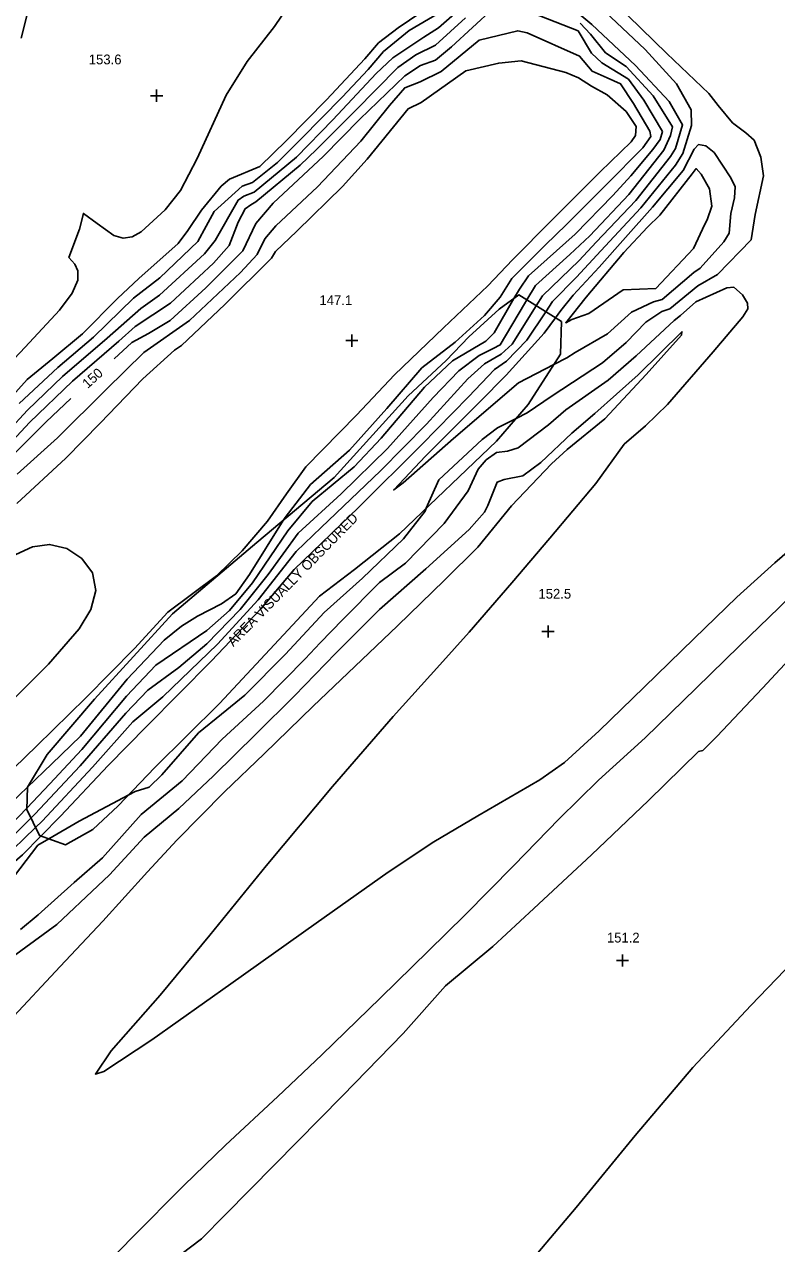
# Model space of a CAD drawing. Extents: x 1475150 to 2003689, y 770235 to 1112803.
# Drawn here: x 2002077.7 to 2002231.5, y 772192.1 to 772441.5 of the extents above; entities that cross this region are included whole.
import ezdxf

# ---------------------------------------------------------------- set-up
doc = ezdxf.new("R2010")
doc.units = 0
for name, color, linetype in [('RD_DTM_Major1', 7, 'Continuous'), ('RD_DTM_Major1_Lbl', 7, 'Continuous'), ('RD_DTM_Major2', 7, 'Continuous'), ('RD_DTM_Minor1', 7, 'Continuous'), ('RD_DTM_Minor2', 7, 'Continuous'), ('RD_DTM_Obscure', 7, 'Continuous'), ('RD_DTM_Spot_Elev', 7, 'Continuous'), ('RD_TX_Misc1', 7, 'Continuous')]:
    doc.layers.add(name, color=color, linetype=linetype)

msp = doc.modelspace()

# ---------------------------------------------------------------- linework, layer by layer
at = {"layer": 'RD_DTM_Major1'}
for points in [[(2002096.04, 772373.12), (2002099.71, 772376.42), (2002103.12, 772378.27), (2002107.53, 772380.93), (2002114.78, 772387.62), (2002122.38, 772395.21), (2002125.05, 772400.79), (2002128.57, 772404.93), (2002138.89, 772414.53), (2002146.31, 772422.13), (2002155.47, 772431), (2002158.68, 772433.07), (2002161.76, 772434.21), (2002165.01, 772436.89), (2002173.6, 772444.79)], [(2002179.95, 772444.48), (2002190.92, 772440.2), (2002193.69, 772435.61), (2002195.75, 772433.64), (2002201.26, 772430.28), (2002204.37, 772426.01), (2002208.16, 772419.59), (2002207.7, 772417.93), (2002206.18, 772415.89), (2002201.68, 772410.53), (2002198.01, 772406.51), (2002190.33, 772398.57), (2002180.81, 772390.09), (2002178.92, 772387.35), (2002177.81, 772385.43)], [(2002217.31, 772401.51), (2002218.28, 772404.32), (2002217.81, 772407.84), (2002216.1, 772410.85), (2002215.09, 772411.99), (2002214.27, 772410.95), (2002207.62, 772402.48), (2002205.14, 772400.05), (2002200.29, 772394.87), (2002192.57, 772385.71), (2002188.41, 772380.47), (2002189.65, 772381.12), (2002193.13, 772382.33), (2002200.14, 772387.17), (2002206.84, 772387.49), (2002214.51, 772395.67), (2002216.84, 772400.64), (2002217.31, 772401.51)], [(2002074.09, 772352.16), (2002082.18, 772360.19), (2002087.21, 772364.99)], [(2002078.21, 772281.19), (2002073.27, 772275.97)]]:
    msp.add_lwpolyline(points, dxfattribs=at)
at = {"layer": 'RD_DTM_Major2'}
msp.add_lwpolyline([(2002177.81, 772385.43), (2002173.77, 772378.43), (2002172.03, 772376.73), (2002165.24, 772372.7), (2002159.55, 772367.31), (2002150.66, 772356.85), (2002145.16, 772350.99), (2002136.57, 772343.89), (2002131.55, 772337.92), (2002124.34, 772327.25), (2002119.68, 772321.58), (2002114.99, 772317.49), (2002104.6, 772310.41), (2002098.59, 772304.06), (2002089.45, 772293.19), (2002082.92, 772286.17), (2002078.21, 772281.19)], dxfattribs=at)
at = {"layer": 'RD_DTM_Minor1'}
for points in [[(2002131.59, 772445.11), (2002128.82, 772441.07), (2002123.24, 772433.92), (2002118.98, 772427), (2002113.04, 772414.08), (2002109.63, 772407.52), (2002106.51, 772403.59), (2002101.57, 772399.04), (2002099.77, 772398.07), (2002097.91, 772397.78), (2002096.02, 772398.33), (2002092.6, 772400.79), (2002089.79, 772402.84), (2002088.99, 772399.64), (2002086.83, 772393.81), (2002088.06, 772392.44), (2002088.65, 772391.12), (2002088.61, 772389.2), (2002087.46, 772386.52), (2002084.9, 772383.04), (2002077.87, 772375.5), (2002071.07, 772368.29), (2002063.39, 772359.35)], [(2002071.11, 772360.96), (2002078.3, 772368.83), (2002083.55, 772373.16), (2002089.61, 772378.22), (2002096.76, 772385.42), (2002101.13, 772389.51), (2002109.13, 772396.69), (2002111.13, 772399.33), (2002113.95, 772403.51), (2002117.98, 772408.38), (2002119.66, 772409.86), (2002125.85, 772412.44), (2002131.34, 772417.74), (2002139.46, 772426.08), (2002147.34, 772434.43), (2002150.13, 772437.76), (2002154.11, 772440.78), (2002163.58, 772447.26)], [(2002078.7, 772445.16), (2002077.07, 772438.66)], [(2002189.74, 772444.85), (2002193.77, 772441.47), (2002202.64, 772433.09), (2002209.55, 772425.74), (2002212.28, 772420.92), (2002210.82, 772416.09), (2002209.84, 772414.47), (2002202.73, 772405.48), (2002194.62, 772396.92), (2002191.18, 772393.22), (2002183.65, 772386), (2002182.36, 772383.94)], [(2002070.24, 772353.89), (2002078.33, 772362.6), (2002085.51, 772369.5), (2002094.66, 772377.31), (2002101.52, 772383.41), (2002105.35, 772386.08), (2002114.53, 772394.57), (2002116.75, 772397.28), (2002121.43, 772405.55), (2002122.61, 772406.36), (2002124.69, 772407.19), (2002133.34, 772414.37), (2002140.79, 772422), (2002149.66, 772431.44), (2002153.02, 772434.67), (2002159.41, 772438.86), (2002162.38, 772440.8), (2002166.23, 772444.11)], [(2002071.72, 772352.54), (2002078.79, 772360.03), (2002087.55, 772368.55), (2002097.04, 772376.73), (2002100.34, 772379.71), (2002107.59, 772384.5), (2002116.35, 772392.69), (2002119.57, 772396.26), (2002121.44, 772401.04), (2002122.88, 772403.8), (2002124.04, 772404.56), (2002125.01, 772405.23), (2002134.13, 772412.67), (2002137.47, 772415.91), (2002145.32, 772423.85), (2002154.08, 772432.7), (2002157.78, 772435.3), (2002161.74, 772437.25), (2002167.9, 772442.84)], [(2002076.66, 772363.92), (2002084.53, 772371.33), (2002091.86, 772377.51), (2002100.03, 772385.49), (2002105.41, 772389.65), (2002113.15, 772397.09), (2002114.88, 772400.25), (2002116.55, 772403.2), (2002122.24, 772408.39), (2002124.37, 772409.15), (2002129.48, 772413.28), (2002134.31, 772418.11), (2002142.72, 772426.63), (2002148.01, 772432.3), (2002151.15, 772435.95), (2002156.36, 772440.23), (2002162.35, 772443.76)], [(2002178.25, 772360.88), (2002180.54, 772362.03), (2002185.62, 772365.54), (2002195.92, 772372.24), (2002200.73, 772376.4), (2002204.79, 772380.57), (2002208.08, 772382.75), (2002209.66, 772383.31), (2002215.38, 772388.04), (2002219.45, 772390.32), (2002226.3, 772397.41), (2002227.11, 772402.6), (2002228.85, 772410.53), (2002228.26, 772414.31), (2002226.92, 772417.81), (2002225.23, 772419.29), (2002222.51, 772421.38), (2002219.6, 772424.91), (2002217.66, 772427.33), (2002209.1, 772435.53), (2002201.18, 772443.27)], [(2002196.46, 772444.04), (2002204.64, 772436.37), (2002211.05, 772429.36), (2002214.03, 772424.05), (2002214.12, 772420.83), (2002212.36, 772415.12), (2002210.86, 772412.69), (2002203.76, 772403.97), (2002195.6, 772395.16), (2002190.63, 772389.78), (2002185.71, 772384.8), (2002184.32, 772382.72)], [(2002076.26, 772349.52), (2002084.5, 772356.9), (2002094.41, 772366.82), (2002102.14, 772374.41), (2002111.48, 772380.94), (2002121.91, 772390.77), (2002125.32, 772394.46), (2002126.86, 772397.64), (2002129.1, 772400.27), (2002137.67, 772408.29), (2002146.49, 772417.59), (2002152.34, 772424.9), (2002155.48, 772428.52), (2002158.65, 772429.75), (2002162.91, 772431.86), (2002170.72, 772438.3), (2002178.6, 772440.21), (2002180.5, 772439.79), (2002191.22, 772434.97), (2002193.78, 772431.93), (2002196.88, 772430.55), (2002199.61, 772429.36), (2002202.29, 772425.34), (2002205.62, 772419.68), (2002205.78, 772418.59), (2002204.18, 772416.27), (2002196.71, 772408.74), (2002188.55, 772400.55), (2002184.21, 772396.32), (2002177.4, 772389.54), (2002174.99, 772385.7), (2002171.78, 772381.95), (2002165.77, 772376.49), (2002159.01, 772371.22), (2002151.82, 772362.95), (2002144.17, 772354.4), (2002136.2, 772347.35), (2002131.01, 772340.64), (2002130.62, 772340.02)], [(2002191.35, 772441.74), (2002193.47, 772439.52), (2002196.55, 772435.66), (2002200.75, 772432.87), (2002206.26, 772426.91), (2002210.23, 772420.57), (2002209.84, 772418.8), (2002208.47, 772415.78), (2002201.31, 772406.68), (2002193.3, 772398.24), (2002189.21, 772394.42), (2002182.2, 772388.08), (2002180.45, 772385.13)], [(2002076.18, 772343.51), (2002086.22, 772352.77), (2002093.24, 772359.95), (2002101.96, 772369.01), (2002108.38, 772374.85), (2002109.84, 772375.84), (2002118.72, 772384.18), (2002128.22, 772393.66), (2002129.06, 772395.01), (2002133.39, 772399.19), (2002142.75, 772408.34), (2002147.78, 772413.93), (2002156.15, 772424.23), (2002158.82, 772425.49), (2002167.95, 772432.02), (2002174.72, 772433.57), (2002179.28, 772434.05), (2002188.44, 772431.66), (2002191.04, 772430.57), (2002193.64, 772428.89), (2002196.87, 772427.08), (2002200.75, 772423.69), (2002202.83, 772420.62), (2002202.68, 772418.75), (2002201.77, 772417.45), (2002195.43, 772411.37), (2002185.56, 772401.42), (2002177.5, 772393.35)], [(2002185.96, 772371.92), (2002188.62, 772373.3), (2002190.36, 772374.37), (2002196.91, 772378.19), (2002201.82, 772382.66), (2002206.35, 772384.74), (2002208.1, 772385.25), (2002214.57, 772390.74), (2002215.91, 772391.63), (2002220.73, 772397), (2002221.79, 772398.81), (2002222.17, 772402.85), (2002222.94, 772405.99), (2002223.07, 772408.28), (2002222.15, 772410.12), (2002218.73, 772415.3), (2002217.02, 772416.68), (2002215.56, 772416.91), (2002214.64, 772415.96), (2002212.42, 772411.63), (2002206.12, 772404.1), (2002200.62, 772397.93), (2002195.26, 772391.83), (2002189.91, 772386.1), (2002187.37, 772382.97), (2002186.29, 772381.49)], [(2002177.5, 772393.35), (2002172.48, 772388.05), (2002163.38, 772379.41), (2002153.38, 772369.84), (2002145.64, 772361.53), (2002135.23, 772351.02), (2002131.31, 772345.44), (2002127.39, 772339.88), (2002122.24, 772333.8), (2002116.96, 772328.7), (2002107.03, 772321.27), (2002100.25, 772313.84), (2002090.27, 772303.72), (2002080.25, 772293.93), (2002070.74, 772284.71)], [(2002076.92, 772256.32), (2002080.55, 772259.34), (2002087.89, 772265.99), (2002093.69, 772270.98), (2002101.56, 772279.9), (2002109.98, 772286.79), (2002118.14, 772295.3), (2002126.62, 772303.08), (2002135.13, 772311.7), (2002138.16, 772315.01), (2002142.8, 772319.77), (2002150.35, 772327.3), (2002155.62, 772331.27), (2002163.51, 772339.37), (2002168.48, 772346.09), (2002170.47, 772350.49), (2002172.12, 772352.41), (2002174.23, 772353.91), (2002176.51, 772354.21), (2002178.65, 772354.86), (2002184.91, 772359.58), (2002188.41, 772362.62), (2002197.08, 772368.74), (2002202.77, 772373.71), (2002210.6, 772380.9), (2002211.87, 772381.96), (2002214.99, 772384.72), (2002221.35, 772387.62), (2002222.79, 772387.72), (2002224.51, 772386.19), (2002225.58, 772384.47), (2002225.61, 772383.29), (2002224.59, 772381.66), (2002218.53, 772374.52), (2002209.19, 772363.73), (2002204.69, 772359.36), (2002200.32, 772355.61), (2002194.55, 772347.59), (2002185.12, 772336.39), (2002177.4, 772327.27), (2002168.67, 772317.18), (2002162.64, 772310.49), (2002153.12, 772299.89), (2002140.7, 772285.61), (2002127.14, 772269.36), (2002115.62, 772255.22), (2002105.5, 772242.93), (2002095.45, 772231.51), (2002092.24, 772226.77), (2002093.93, 772227.28), (2002103.79, 772233.79), (2002119.93, 772245.26), (2002137.35, 772257.68), (2002152.06, 772268.07), (2002161.41, 772274.26), (2002170.44, 772279.61), (2002183.09, 772286.99), (2002188.13, 772290.51), (2002195.23, 772296.98), (2002204.43, 772305.9), (2002214.69, 772315.91), (2002223.4, 772324.3), (2002231.13, 772331.38), (2002241.19, 772340.03)], [(2002179.66, 772349.17), (2002183.29, 772351.87), (2002189.64, 772357.85), (2002194.35, 772361.88), (2002203.18, 772369.83), (2002212.16, 772378.62), (2002212.04, 772377.9), (2002204.85, 772369.86), (2002196.42, 772360.8), (2002188.71, 772354.52), (2002185.46, 772351.62), (2002177.31, 772343.02), (2002170.41, 772334.58), (2002163.6, 772327.81), (2002153.97, 772318.48), (2002145.26, 772310.15), (2002136.79, 772302.02), (2002126.75, 772292.28), (2002118.62, 772284.51), (2002108.88, 772274.64), (2002102.91, 772268.15), (2002093.76, 772258.03), (2002085.06, 772248.79), (2002074.59, 772237.62)], [(2002276.58, 772362.12), (2002266.32, 772354.73), (2002260.37, 772349.29), (2002252.03, 772341.49), (2002240.26, 772330.39), (2002232.01, 772322.25), (2002223.95, 772314.38), (2002215.1, 772305.69), (2002204.66, 772295.53), (2002195.07, 772286.9), (2002187.09, 772278.99), (2002177.81, 772269.45), (2002167.77, 772259.31), (2002160.35, 772251.99), (2002150.56, 772242.4), (2002138.51, 772230.74), (2002129.51, 772222.2), (2002118.86, 772212.25), (2002110.3, 772203.95), (2002099.77, 772193.37), (2002090.79, 772184.17)], [(2002075.19, 772250.69), (2002084.33, 772257.36), (2002092.74, 772265.29), (2002095.14, 772267.51), (2002102.21, 772275.22), (2002109.27, 772281.08), (2002116.4, 772287.78), (2002125.11, 772296.4), (2002132.95, 772304.13), (2002141.42, 772312.9), (2002150.29, 772321.79), (2002159.82, 772330.16), (2002168.67, 772338.19), (2002171.79, 772341.71), (2002172.45, 772343.11), (2002174.35, 772347.86), (2002175.81, 772348.38), (2002179.66, 772349.17)], [(2002099.05, 772283.88), (2002100.34, 772284.56), (2002103.23, 772285.49), (2002105.79, 772288.02), (2002113.29, 772296.56), (2002118.03, 772300.38), (2002122.8, 772304.3), (2002131.12, 772312.66), (2002139.04, 772321.17), (2002146.86, 772328.24), (2002155.25, 772336.24), (2002159.63, 772341.93), (2002159.89, 772342.52)], [(2002075.96, 772333.04), (2002079.4, 772334.62), (2002082.88, 772335.12), (2002086.38, 772334.26), (2002089.47, 772332.22), (2002091.64, 772329.28), (2002092.35, 772325.72), (2002091.29, 772321.82), (2002088.89, 772317.85), (2002082.64, 772310.6), (2002075.21, 772303.18)], [(2002178.23, 772184.86), (2002190.56, 772199.51), (2002202.6, 772214.24), (2002214.41, 772228.14), (2002226.27, 772240.78), (2002236.67, 772251.63), (2002244.51, 772260.7), (2002251.91, 772270.34), (2002260.72, 772282.21), (2002270.71, 772296.09), (2002272.81, 772300.06), (2002273.13, 772303.37), (2002273.35, 772310.84), (2002273.96, 772315.75), (2002274.57, 772324.38), (2002275.07, 772325.12), (2002276.06, 772325.35), (2002286.66, 772324.42), (2002289.78, 772324.56), (2002292.07, 772325.07)], [(2002103.51, 772185.18), (2002113.91, 772193.08), (2002118.75, 772197.99), (2002128.84, 772208.19), (2002142.79, 772222.33), (2002155.15, 772235.1), (2002163.84, 772244.84), (2002173.47, 772252.84), (2002181.86, 772260.67), (2002193.64, 772271.6), (2002205.31, 772282.72), (2002215.56, 772292.75), (2002216.41, 772292.96), (2002219.32, 772295.83), (2002228.61, 772305.7), (2002242.2, 772320.34)], [(2002078.36, 772285.47), (2002073.27, 772280.57)], [(2002079.05, 772279.12), (2002072.63, 772272.72)], [(2002081.09, 772275.44), (2002077.35, 772271.64), (2002067.45, 772263.1), (2002060.52, 772256.76), (2002054.59, 772250.74), (2002045.92, 772241.9), (2002044.32, 772239.81), (2002045.13, 772240.07), (2002046.74, 772241.17), (2002053.1, 772245.65), (2002059.45, 772252.49), (2002066.77, 772257.51), (2002070.92, 772261.24), (2002073.12, 772263.9), (2002080.48, 772273.61), (2002082.68, 772274.89)], [(2002079.98, 772277.2), (2002073.08, 772270.5)]]:
    msp.add_lwpolyline(points, dxfattribs=at)
at = {"layer": 'RD_DTM_Minor2'}
for points in [[(2002180.45, 772385.13), (2002179.98, 772384.34), (2002175.01, 772375.95), (2002173.55, 772375.17), (2002170.72, 772373.78), (2002166.51, 772370.66), (2002161.32, 772365.18), (2002151.99, 772354.76), (2002142.47, 772345.5), (2002133.66, 772337.44), (2002127.56, 772328.99), (2002121.82, 772321.82), (2002115.05, 772314.79), (2002109.31, 772309.94), (2002102.92, 772305.29), (2002098.47, 772300.59), (2002089.12, 772289.82), (2002079.83, 772279.91), (2002079.05, 772279.12)], [(2002182.36, 772383.94), (2002177.45, 772376.11), (2002175.2, 772374.06), (2002171.76, 772372.08), (2002168.39, 772369), (2002159.91, 772359.75), (2002150.54, 772350.19), (2002138.4, 772338.56), (2002133.28, 772333.7), (2002125.51, 772323.77), (2002117.18, 772314.73), (2002106.04, 772303.94), (2002099.89, 772298.83), (2002091.66, 772289.56), (2002081.34, 772278.51), (2002079.98, 772277.2)], [(2002184.32, 772382.72), (2002180.43, 772376.89), (2002176.28, 772372.62), (2002173.84, 772370.91), (2002168.54, 772365.33), (2002158.93, 772355.52), (2002146, 772342.67), (2002132.9, 772329.96), (2002126.1, 772322.03), (2002115.94, 772311.3), (2002102.78, 772297.95), (2002094.84, 772289.92), (2002085.1, 772279.52), (2002081.09, 772275.44)], [(2002186.29, 772381.49), (2002184.01, 772378.34), (2002176.23, 772369.74), (2002170.74, 772364.19), (2002159.73, 772353.18), (2002153.23, 772346.27), (2002155.14, 772347.7), (2002165.47, 772356.82), (2002178.71, 772368.18), (2002185.96, 772371.92)], [(2002159.89, 772342.52), (2002162.45, 772348.33), (2002171.28, 772356.58), (2002174.45, 772358.97), (2002178.25, 772360.88)], [(2002130.62, 772340.02), (2002123.76, 772328.99), (2002120.93, 772325), (2002118.03, 772323), (2002113.08, 772320.47), (2002109.87, 772318.42), (2002106.29, 772315.54), (2002098.71, 772307.54), (2002089.2, 772295.9), (2002083.31, 772290.23), (2002078.36, 772285.47)], [(2002082.68, 772274.89), (2002088.9, 772278.5), (2002099.05, 772283.88)]]:
    msp.add_lwpolyline(points, dxfattribs=at)
at = {"layer": 'RD_DTM_Obscure'}
msp.add_lwpolyline([(2002187.55, 772380.71), (2002187.33, 772374.06), (2002180.73, 772363.76), (2002174.25, 772356.24), (2002154.41, 772337.29), (2002145.24, 772329.98), (2002138.05, 772324.55), (2002130.67, 772316.62), (2002117.59, 772302.55), (2002104.39, 772289.47), (2002096.92, 772281.64), (2002091.71, 772276.82), (2002086.15, 772273.68), (2002080.78, 772275.55), (2002078.2, 772280.87), (2002078.37, 772285.5), (2002082.36, 772292.15), (2002092.04, 772303.48), (2002107.99, 772320.89), (2002125.25, 772335.49), (2002141.07, 772348.84), (2002156.17, 772365.52), (2002163.97, 772372.73), (2002168.59, 772377.59), (2002174.82, 772383.28), (2002178.81, 772386.15), (2002187.55, 772380.71)], dxfattribs=at)
at = {"layer": 'RD_DTM_Spot_Elev'}
for p, q in [((2002104.74, 772425.65), (2002104.74, 772428.15)), ((2002103.49, 772426.9), (2002105.99, 772426.9)), ((2002144.67, 772375.57), (2002144.67, 772378.07)), ((2002143.42, 772376.82), (2002145.92, 772376.82)), ((2002184.79, 772316.05), (2002184.79, 772318.55)), ((2002183.54, 772317.3), (2002186.04, 772317.3)), ((2002200, 772248.75), (2002200, 772251.25)), ((2002198.75, 772250), (2002201.25, 772250))]:
    msp.add_line(p, q, dxfattribs=at)

# ---------------------------------------------------------------- texts
at = {"layer": 'RD_DTM_Major1_Lbl'}
msp.add_text('150', height=2, rotation=41.9948, dxfattribs=at).set_placement((2002090.65, 772366.91))
at = {"layer": 'RD_DTM_Spot_Elev'}
for s, p in [('153.6', (2002090.88, 772433.33)), ('147.1', (2002138.04, 772384.09)), ('152.5', (2002182.82, 772324.03)), ('151.2', (2002196.82, 772253.69))]:
    msp.add_text(s, height=2, dxfattribs=at).set_placement(p)
at = {"layer": 'RD_TX_Misc1'}
msp.add_text('AREA VISUALLY OBSCURED', height=2, rotation=45.6228, dxfattribs=at).set_placement((2002120.43, 772314.11))

doc.saveas('drawing.dxf')
